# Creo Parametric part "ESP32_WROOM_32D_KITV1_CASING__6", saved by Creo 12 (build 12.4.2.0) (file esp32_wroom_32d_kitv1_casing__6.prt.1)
Units: Custom; MM, KILOGRAM, SECS

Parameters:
  PTC_WM_ITERATION = "0"
  PTC_WM_VERSION = "-.0"
  PTC_WM_LIFECYCLE_STATE = "In Work"
  PTC_WM_LIFECYCLE = "MO_CADDocument"
  PTC_WM_CREATED_BY = "Maximilian Roepper (Z0017RMS: MO)"
  PTC_WM_CREATED_ON = "18-Sep-26 11:36:42 AM"
  PTC_WM_MODIFIED_BY = "Maximilian Roepper (Z0017RMS: MO)"
  PTC_WM_MODIFIED_ON = "18-Sep-26 11:36:46 AM"
  PDMLINKNUMBER = "PDM000071455251"
  PTC_WM_NAME = "esp32_wroom_32d_kitv1_casing__6.prt"
  PTC_WM_NUMBER = "PDM000071455251"

Other parameters: WEIGHT, WEIGHT_FACTOR, WEIGHT_ADD, _MASS_TEMP, _DIFF_TEMP, MC_ERRORS, SUPPLIER

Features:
  1. coordinate system
  2. datum plane "PRT_YZ"
  3. datum plane "PRT_XY"
  4. datum plane "PRT_XZ"
  5. coordinate system
  6. datum axis
  7. datum axis
  8. datum axis
  9. coordinate system
  10. imported feature
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
Other named items: PRT, SIEMENS_MO, DRW_VIEW_ORG, PRT_X, PRT_Y, PRT_Z, CS0, ROUGH_GROB

Layers: 00_STD_CSYS-KSYS, 01_STD_PLANES-EBENEN, 02_STD_AXES-ACHSEN, 03_STD_CSYS-KSYS, 24_IMPORT_FEAT-IMPORT_KE

Surfaces: 6 plane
